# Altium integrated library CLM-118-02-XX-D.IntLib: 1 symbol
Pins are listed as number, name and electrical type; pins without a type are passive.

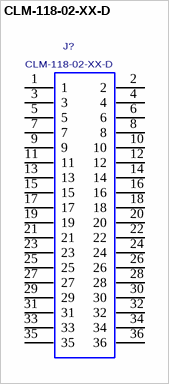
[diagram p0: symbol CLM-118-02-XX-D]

## CLM-118-02-XX-D
designator J?
Low profile Socket Strip, 1 mm Pitch, 36 Pins.; MANUFACTURER: SAMTEC
footprint CLM-118-02-XX-D
pins: 1, 2, 3, 4, 5, 6, 7, 8, 9, 10, 11, 12, 13, 14, 15, 16, 17, 18, 19, 20, 21, 22, 23, 24, 25, 26, 27, 28, 29, 30, 31, 32, 33, 34, 35, 36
